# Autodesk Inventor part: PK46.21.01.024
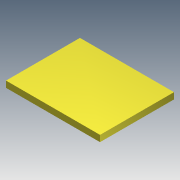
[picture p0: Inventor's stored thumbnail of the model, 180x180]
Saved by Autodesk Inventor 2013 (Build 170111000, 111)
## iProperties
Created: 2005-04
Part Number: PK46.21.01.024
Material: Steel, Mild
Document SubType Name: Modeling
Designer: salex
Manufacturer: Standard
Standards Organization: Custom
Density: 7.86 g/cm^3
Author: salex
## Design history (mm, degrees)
sketch "Эскиз1"
  geometry: L1 (0, 0)-(150, 0); L2 (150, 0)-(150, 118); L3 (150, 118)-(0, 118); L4 (0, 118)-(0, 0)
  constraints: 8 end point, 2 parallel, 1 horizontal, 1 perpendicular, 1 other
  dimensions: "d0" = 150 distance of L1.start L1.end; "d1" = 118 distance of L3.end L1.start
extrude "Выдавливание1" new body sketch "Эскиз1" distance "d2" = 10; taper "d3" = 0 deg
body "Solid1"
